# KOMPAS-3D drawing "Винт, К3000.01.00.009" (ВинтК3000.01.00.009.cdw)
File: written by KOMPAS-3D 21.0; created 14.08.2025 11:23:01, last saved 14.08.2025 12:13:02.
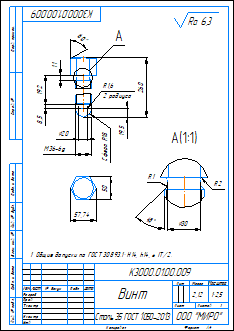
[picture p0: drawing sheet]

Sheet 1: A4, portrait

Document properties: Автор: Kolov; Параметр неуказанной шероховатости: Ra 6,3; Масса: 2.124; Полное имя файла: ..\от тм\Стрела 2\Винт 7006-1070 ГОСТ 13435-68.m3d

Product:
- Part/product: Винт  | designation К3000.01.00.009
    Материал: Сталь 35 ГОСТ 1050-2013 (density 7826 kg/m3)
    Масса: 2.124
  - Body: Тело 1
      Масса: 2.330049

Title block, sheet 1: Наименование: Винт; designation: К3000.01.00.009; Материал: Сталь 35 ГОСТ 1050-2013; Масса: 2,12; Количество листов документа: 1; organisation: ООО "МИРО"; Форматы листов документа: A4; stored path: C:\Users\ShavarinML\Desktop\Стапель\2D\ВинтК3000.01.00.009.cdw

Views: Спереди 1, Спереди, Проекционный вид 2, Выносной элемент 3, Выносной элемент А, Выносной элемент
Referenced files in C:\Users\ShavarinML\Desktop\Стапель\от тм\Стрела 2\: Винт 7006-1070 ГОСТ 13435-68.m3d
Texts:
  Сфера
  Ra 6,3
  К3000.01.00.009 Винт
Dimensions and other numbers on the sheet: 260; 19,5; 18; 20; 8,5; 1,6; 2 радиуса; 192; -6g; 36; 11; 57,74; 50; 30; 1; 2; 1:2,5; 2,12

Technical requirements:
  Общие допуски по ГОСТ 30893.1: H14, h14,   IT/2.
